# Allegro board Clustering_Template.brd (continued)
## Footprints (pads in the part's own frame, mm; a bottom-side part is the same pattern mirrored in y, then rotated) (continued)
CONM38P_MICTOR_1
  round 1.27 hole 2.388 unplated: (-11.43,0)
  oval 0.457x1.27 smd: 1(-5.715,-3.531) 2(-5.08,-3.531) 3(-4.445,-3.531) 4(-3.81,-3.531) 5(-3.175,-3.531) 6(-2.54,-3.531) 7(-1.905,-3.531) 8(-1.27,-3.531) 9(-0.635,-3.531) 10(0,-3.531) 11(0.635,-3.531) 12(1.27,-3.531) 13(1.905,-3.531) 14(2.54,-3.531) 15(3.175,-3.531) 16(3.81,-3.531) 17(4.445,-3.531) 18(5.08,-3.531) 19(5.715,-3.531) 20(5.715,3.531) 21(5.08,3.531) 22(4.445,3.531) 23(3.81,3.531) 24(3.175,3.531) 25(2.54,3.531) 26(1.905,3.531) 27(1.27,3.531) 28(0.635,3.531) 29(0,3.531) 30(-0.635,3.531) 31(-1.27,3.531) 32(-1.905,3.531) 33(-2.54,3.531) 34(-3.175,3.531) 35(-3.81,3.531) 36(-4.445,3.531) 37(-5.08,3.531) 38(-5.715,3.531)
  round 1.194 hole 0.813: 39(-5.08,0) 40(-2.54,0) 41(0,0) 42(2.54,0) 43(5.08,0)
CONM_BGA200_1
  round 1.27 hole 1.448 unplated: (-19.652,8.499) (20.137,0)
  round 1.651 hole 1.27: (-19.652,-6.35) (19.667,4)
  round 0.61 smd: A1(-17.064,-6.749) A3(-15.314,-6.749) A5(-13.564,-6.749) A7(-11.814,-6.749) A9(-10.063,-6.749) A11(-8.313,-6.749) A13(-6.563,-6.749) A15(-4.813,-6.749) A17(-3.063,-6.749) A19(-1.313,-6.749) A21(0.437,-6.749) A23(2.187,-6.749) A25(3.937,-6.749) A27(5.687,-6.749) A29(7.437,-6.749) A31(9.187,-6.749) A33(10.937,-6.749) A35(12.687,-6.749) A37(14.437,-6.749) A39(16.187,-6.749) B2(-16.187,-5.999) B4(-14.437,-5.999) B6(-12.687,-5.999) B8(-10.937,-5.999) B10(-9.187,-5.999) B12(-7.437,-5.999) B14(-5.687,-5.999) B16(-3.937,-5.999) B18(-2.187,-5.999) B20(-0.437,-5.999) B22(1.313,-5.999) B24(3.063,-5.999) B26(4.813,-5.999) B28(6.563,-5.999) B30(8.313,-5.999) B32(10.063,-5.999) B34(11.814,-5.999) B36(13.564,-5.999) B38(15.314,-5.999) B40(17.064,-5.999) C1(-17.064,-5.25) C3(-15.314,-5.25) C5(-13.564,-5.25) C7(-11.814,-5.25) C9(-10.063,-5.25) C11(-8.313,-5.25) C13(-6.563,-5.25) C15(-4.813,-5.25) C17(-3.063,-5.25) C19(-1.313,-5.25) C21(0.437,-5.25) C23(2.187,-5.25) C25(3.937,-5.25) C27(5.687,-5.25) C29(7.437,-5.25) C31(9.187,-5.25) C33(10.937,-5.25) C35(12.687,-5.25) C37(14.437,-5.25) C39(16.187,-5.25) D2(-16.187,-4.501) D4(-14.437,-4.501) D6(-12.687,-4.501) D8(-10.937,-4.501) D10(-9.187,-4.501) D12(-7.437,-4.501) D14(-5.687,-4.501) D16(-3.937,-4.501) D18(-2.187,-4.501) D20(-0.437,-4.501) D22(1.313,-4.501) D24(3.063,-4.501) D26(4.813,-4.501) D28(6.563,-4.501) D30(8.313,-4.501) D32(10.063,-4.501) D34(11.814,-4.501) D36(13.564,-4.501) D38(15.314,-4.501) D40(17.064,-4.501) E1(-17.064,-3.749) E3(-15.314,-3.749) E5(-13.564,-3.749) E7(-11.814,-3.749) E9(-10.063,-3.749) E11(-8.313,-3.749) E13(-6.563,-3.749) E15(-4.813,-3.749) E17(-3.063,-3.749) E19(-1.313,-3.749) E21(0.437,-3.749) E23(2.187,-3.749) E25(3.937,-3.749) E27(5.687,-3.749) E29(7.437,-3.749) E31(9.187,-3.749) E33(10.937,-3.749) E35(12.687,-3.749) E37(14.437,-3.749) E39(16.187,-3.749) F2(-16.187,-3) F4(-14.437,-3) F6(-12.687,-3) F8(-10.937,-3) F10(-9.187,-3) F12(-7.437,-3) F14(-5.687,-3) F16(-3.937,-3) F18(-2.187,-3) F20(-0.437,-3) F22(1.313,-3) F24(3.063,-3) F26(4.813,-3) F28(6.563,-3) F30(8.313,-3) F32(10.063,-3) F34(11.814,-3) F36(13.564,-3) F38(15.314,-3) F40(17.064,-3) G1(-17.064,-2.25) G3(-15.314,-2.25) G5(-13.564,-2.25) G7(-11.814,-2.25) G9(-10.063,-2.25) G11(-8.313,-2.25) G13(-6.563,-2.25) G15(-4.813,-2.25) G17(-3.063,-2.25) G19(-1.313,-2.25) G21(0.437,-2.25) G23(2.187,-2.25) G25(3.937,-2.25) G27(5.687,-2.25) G29(7.437,-2.25) G31(9.187,-2.25) G33(10.937,-2.25) G35(12.687,-2.25) G37(14.437,-2.25) G39(16.187,-2.25) H2(-16.187,-1.501) H4(-14.437,-1.501) H6(-12.687,-1.501) H8(-10.937,-1.501) H10(-9.187,-1.501) H12(-7.437,-1.501) H14(-5.687,-1.501) H16(-3.937,-1.501) H18(-2.187,-1.501) H20(-0.437,-1.501) H22(1.313,-1.501) H24(3.063,-1.501) H26(4.813,-1.501) H28(6.563,-1.501) H30(8.313,-1.501) H32(10.063,-1.501) H34(11.814,-1.501) H36(13.564,-1.501) H38(15.314,-1.501) H40(17.064,-1.501) J1(-17.064,-0.749) J3(-15.314,-0.749) J5(-13.564,-0.749) J7(-11.814,-0.749) J9(-10.063,-0.749) J11(-8.313,-0.749) J13(-6.563,-0.749) J15(-4.813,-0.749) J17(-3.063,-0.749) J19(-1.313,-0.749) J21(0.437,-0.749) J23(2.187,-0.749) J25(3.937,-0.749) J27(5.687,-0.749) J29(7.437,-0.749) J31(9.187,-0.749) J33(10.937,-0.749) J35(12.687,-0.749) J37(14.437,-0.749) J39(16.187,-0.749) K2(-16.187,0) K4(-14.437,0) K6(-12.687,0) K8(-10.937,0) K10(-9.187,0) K12(-7.437,0) K14(-5.687,0) K16(-3.937,0) K18(-2.187,0) K20(-0.437,0) K22(1.313,0) K24(3.063,0) K26(4.813,0) K28(6.563,0) K30(8.313,0) K32(10.063,0) K34(11.814,0) K36(13.564,0) K38(15.314,0) K40(17.064,0) L1(-17.064,0.749) L3(-15.314,0.749) L5(-13.564,0.749) L7(-11.814,0.749) L9(-10.063,0.749) L11(-8.313,0.749) L13(-6.563,0.749) L15(-4.813,0.749) L17(-3.063,0.749) L19(-1.313,0.749) L21(0.437,0.749) L23(2.187,0.749) L25(3.937,0.749) L27(5.687,0.749) L29(7.437,0.749) L31(9.187,0.749) L33(10.937,0.749) L35(12.687,0.749) L37(14.437,0.749) L39(16.187,0.749) M2(-16.187,1.501) M4(-14.437,1.501) M6(-12.687,1.501) M8(-10.937,1.501) M10(-9.187,1.501) M12(-7.437,1.501) M14(-5.687,1.501) M16(-3.937,1.501) M18(-2.187,1.501) M20(-0.437,1.501) M22(1.313,1.501) M24(3.063,1.501) M26(4.813,1.501) M28(6.563,1.501) M30(8.313,1.501) M32(10.063,1.501) M34(11.814,1.501) M36(13.564,1.501) M38(15.314,1.501) M40(17.064,1.501) N1(-17.064,2.25) N3(-15.314,2.25) N5(-13.564,2.25) N7(-11.814,2.25) N9(-10.063,2.25) N11(-8.313,2.25) N13(-6.563,2.25) N15(-4.813,2.25) N17(-3.063,2.25) N19(-1.313,2.25) N21(0.437,2.25) N23(2.187,2.25) N25(3.937,2.25) N27(5.687,2.25) N29(7.437,2.25) N31(9.187,2.25) N33(10.937,2.25) N35(12.687,2.25) N37(14.437,2.25) N39(16.187,2.25) P2(-16.187,3) P4(-14.437,3) P6(-12.687,3) P8(-10.937,3) P10(-9.187,3) P12(-7.437,3) P14(-5.687,3) P16(-3.937,3) P18(-2.187,3) P20(-0.437,3) P22(1.313,3) P24(3.063,3) P26(4.813,3) P28(6.563,3) P30(8.313,3) P32(10.063,3) P34(11.814,3) P36(13.564,3) P38(15.314,3) P40(17.064,3) R1(-17.064,3.749) R3(-15.314,3.749) R5(-13.564,3.749) R7(-11.814,3.749) R9(-10.063,3.749) R11(-8.313,3.749) R13(-6.563,3.749) R15(-4.813,3.749) R17(-3.063,3.749) R19(-1.313,3.749) R21(0.437,3.749) R23(2.187,3.749) R25(3.937,3.749) R27(5.687,3.749) R29(7.437,3.749) R31(9.187,3.749) R33(10.937,3.749) R35(12.687,3.749) R37(14.437,3.749) R39(16.187,3.749) T2(-16.187,4.501) T4(-14.437,4.501) T6(-12.687,4.501) T8(-10.937,4.501) T10(-9.187,4.501) T12(-7.437,4.501) T14(-5.687,4.501) T16(-3.937,4.501) T18(-2.187,4.501) T20(-0.437,4.501) T22(1.313,4.501) T24(3.063,4.501) T26(4.813,4.501) T28(6.563,4.501) T30(8.313,4.501) T32(10.063,4.501) T34(11.814,4.501) T36(13.564,4.501) T38(15.314,4.501) T40(17.064,4.501) U1(-17.064,5.25) U3(-15.314,5.25) U5(-13.564,5.25) U7(-11.814,5.25) U9(-10.063,5.25) U11(-8.313,5.25) U13(-6.563,5.25) U15(-4.813,5.25) U17(-3.063,5.25) U19(-1.313,5.25) U21(0.437,5.25) U23(2.187,5.25) U25(3.937,5.25) U27(5.687,5.25) U29(7.437,5.25) U31(9.187,5.25) U33(10.937,5.25) U35(12.687,5.25) U37(14.437,5.25) U39(16.187,5.25) V2(-16.187,5.999) V4(-14.437,5.999) V6(-12.687,5.999) V8(-10.937,5.999) V10(-9.187,5.999) V12(-7.437,5.999) V14(-5.687,5.999) V16(-3.937,5.999) V18(-2.187,5.999) V20(-0.437,5.999) V22(1.313,5.999) V24(3.063,5.999) V26(4.813,5.999) V28(6.563,5.999) V30(8.313,5.999) V32(10.063,5.999) V34(11.814,5.999) V36(13.564,5.999) V38(15.314,5.999) V40(17.064,5.999) W1(-17.064,6.749) W3(-15.314,6.749) W5(-13.564,6.749) W7(-11.814,6.749) W9(-10.063,6.749) W11(-8.313,6.749) W13(-6.563,6.749) W15(-4.813,6.749) W17(-3.063,6.749) W19(-1.313,6.749) W21(0.437,6.749) W23(2.187,6.749) W25(3.937,6.749) W27(5.687,6.749) W29(7.437,6.749) W31(9.187,6.749) W33(10.937,6.749) W35(12.687,6.749) W37(14.437,6.749) W39(16.187,6.749)
HDR1X2RA_SMT_100_1
  rect 1.27x3.175 smd: 1(-1.27,5.283) 2(1.27,5.283)
HDR2X6V_100SMT_1
  round 1.27 hole 1.702 unplated: (-5.08,0) (5.08,0)
  rect 1.27x3.175 smd: 1(-6.35,-2.603) 2(-6.35,2.603) 3(-3.81,-2.603) 4(-3.81,2.603) 5(-1.27,-2.603) 6(-1.27,2.603) 7(1.27,-2.603) 8(1.27,2.603) 9(3.81,-2.603) 10(3.81,2.603) 11(6.35,-2.603) 12(6.35,2.603)
RA0603_4A_1
  rect 1.016x0.508 smd: 1(-0.762,1.199) 2(-0.762,0.399) 3(-0.762,-0.399) 4(-0.762,-1.199) 5(0.762,-1.199) 6(0.762,-0.399) 7(0.762,0.399) 8(0.762,1.199)
RC0603_1
  rect 0.889x0.889 smd: 1(-0.813,0) 2(0.813,0)
RC1206_1
  rect 1.397x1.778 smd: 1(-1.664,0) 2(1.664,0)
SOIC8NB_50_1
  oval 1.905x0.635 smd: 1(-2.578,1.905) 2(-2.578,0.635) 3(-2.578,-0.635) 4(-2.578,-1.905) 5(2.578,-1.905) 6(2.578,-0.635) 7(2.578,0.635) 8(2.578,1.905)
SOT_23_1
  rect 0.762x0.889 smd: 1(-0.94,-1.003) 2(0.94,-1.003) 3(0,1.003)
TO-252AA_1
  rect 1.016x1.524 smd: 1(-2.286,-5.652) 3(2.286,-5.652)
  rect 5.715x6.223 smd: 4(0,1.638)
VREG_400G_14P_1
  round 1.27 hole 4.75 unplated: (-8.89,16.51) (41.91,16.51)
  round 1.295 hole 0.914: 1(0,0) 2(2.54,0) 3(5.08,0) 4(7.62,0) 5(10.16,0) 6(12.7,0) 7(15.24,0) 8(17.78,0) 9(20.32,0) 10(22.86,0) 11(25.4,0) 12(27.94,0) 13(30.48,0) 14(33.02,0)

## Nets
3.3V: C120.2(N2) C121.2(N2) C122.2(N2) C123.2(N2) C124.2(N2) C125.2(N2) C126.2(N2) C127.2(N2) C128.2(N2) C129.2(N2) C130.2(N2) C131.2(N2) C132.2(N2) C133.2(N2) C134.2(N2) C135.2(N2) C136.2(N2) C137.2(N2) C138.2(N2) C139.2(N2) C140.2(N2) C141.2(N2) C142.2(N2) C143.2(N2) C144.2(N2) C145.2(N2) C146.2(N2) C147.2(N2) C148.2(N2) C149.2(N2) C150.2(N2) C151.2(N2) C152.2(N2) C153.2(N2) C154.2(N2) C155.2(N2) C156.2(N2) C157.2(N2) C158.2(N2) C159.2(N2) C160.2(N2) C161.2(N2) C162.2(N2) C163.2(N2) C164.2(N2) C165.2(N2) C166.2(N2) C167.2(N2) C168.2(N2) C169.2(N2) C170.2(N2) C171.2(N2) C172.2(N2) C173.2(N2) C174.2(N2) C175.2(N2) C176.2(N2) C177.2(N2) C178.2(N2) C179.2(N2) C180.2(N2) C181.2(N2) C182.2(N2) C183.2(N2) C256.2(N2) C257.2(N2) C258.2(N2) C259.2(N2) C260.2(N2) C261.2(N2) C262.2(N2) C263.2(N2) C264.2(N2) C265.2(N2) C266.2(N2) C267.2(N2) C268.2(N2) C269.2(N2) C270.2(N2) C271.2(N2) C272.2(N2) C273.2(N2) C274.2(N2) C275.2(N2) C276.2(N2) C277.2(N2) C278.2(N2) C279.2(N2) C280.2(N2) C281.2(N2) C282.2(N2) C283.2(N2) C284.2(N2) C285.2(N2) C286.2(N2) C287.2(N2) C288.2(N2) C289.2(N2) C290.2(N2) C291.2(N2) C292.2(N2) C293.2(N2) C294.2(N2) C295.2(N2) C296.2(N2) C297.2(N2) C298.2(N2) C299.2(N2) C300.2(N2) C301.2(N2) C302.2(N2) C303.2(N2) C304.2(N2) C305.2(N2) C306.2(N2) C307.2(N2) C308.2(N2) C309.2(N2) C310.2(N2) C311.2(N2) C312.2(N2) C313.2(N2) C314.2(N2) C315.2(N2) C316.2(N2) C317.2(N2) C318.2(N2) C319.2(N2) C392.2(N2) C393.2(N2) C394.2(N2) C395.2(N2) C396.2(N2) C397.2(N2) C398.2(N2) C399.2(N2) C400.2(N2) C401.2(N2) C402.2(N2) C403.2(N2) C404.2(N2) C405.2(N2) C406.2(N2) C407.2(N2) C408.2(N2) C409.2(N2) C410.2(N2) C411.2(N2) C412.2(N2) C413.2(N2) C414.2(N2) C415.2(N2) C416.2(N2) C417.2(N2) C418.2(N2) C419.2(N2) C420.2(N2) C421.2(N2) C422.2(N2) C423.2(N2) C424.2(N2) C425.2(N2) C426.2(N2) C427.2(N2) C428.2(N2) C429.2(N2) C430.2(N2) C431.2(N2) C432.2(N2) C433.2(N2) C434.2(N2) C435.2(N2) C436.2(N2) C437.2(N2) C438.2(N2) C439.2(N2) C440.2(N2) C441.2(N2) C442.2(N2) C443.2(N2) C444.2(N2) C445.2(N2) C446.2(N2) C447.2(N2) C448.2(N2) C449.2(N2) C450.2(N2) C451.2(N2) C452.2(N2) C453.2(N2) C454.2(N2) C455.2(N2) C528.2(N2) C529.2(N2) C530.2(N2) C531.2(N2) C532.2(N2) C533.2(N2) C534.2(N2) C535.2(N2) C536.2(N2) C537.2(N2) C538.2(N2) C539.2(N2) C540.2(N2) C541.2(N2) C542.2(N2) C543.2(N2) C544.2(N2) C545.2(N2) C546.2(N2) C547.2(N2) C548.2(N2) C549.2(N2) C550.2(N2) C551.2(N2) C552.2(N2) C553.2(N2) C554.2(N2) C555.2(N2) C556.2(N2) C557.2(N2) C558.2(N2) C559.2(N2) C560.2(N2) C561.2(N2) C562.2(N2) C563.2(N2) C564.2(N2) C565.2(N2) C566.2(N2) C567.2(N2) C568.2(N2) C569.2(N2) C570.2(N2) C571.2(N2) C572.2(N2) C573.2(N2) C574.2(N2) C575.2(N2) C576.2(N2) C577.2(N2) C578.2(N2) C579.2(N2) C580.2(N2) C581.2(N2) C582.2(N2) C583.2(N2) C584.2(N2) C585.2(N2) C586.2(N2) C587.2(N2) C588.2(N2) C589.2(N2) C590.2(N2) C591.2(N2) C664.2(N2) C667.2(N2) C676.2(N2) C677.2(N2) C678.2(N2) C679.2(N2) C703.2(N2) C704.2(N2) C705.2(N2) C706.2(N2) C707.2(N2) C708.2(N2) C709.2(N2) C710.2(N2) C711.2(N2) D1.4(P) D2.4(P) J1.B2 J1.B4 J1.B6 J1.B8 J1.B10 J1.B32 J1.B34 J1.B36 J1.B38 J1.B40 J1.D2 J1.D4 J1.D6 J1.D8 J1.D10 J1.D32 J1.D34 J1.D36 J1.D38 J1.D40 J1.F2 J1.F4 J1.F6 J1.F8 J1.F10 J1.F32 J1.F34 J1.F36 J1.F38 J1.F40 J1.H2 J1.H4 J1.H6 J1.H8 J1.H10 J1.H32 J1.H34 J1.H36 J1.H38 J1.H40 J1.J3 J1.K2 J1.K4 J1.K6 J1.K8 J1.K10 J1.K32 J1.K34 J1.K36 J1.K38 J1.K40 J1.L3 J1.M2 J1.M4 J1.M6 J1.M8 J1.M10 J1.M32 J1.M34 J1.M36 J1.M38 J1.M40 J1.N3 J1.P2 J1.P4 J1.P6 J1.P8 J1.P10 J1.P32 J1.P34 J1.P36 J1.P38 J1.P40 J1.T2 J1.T4 J1.T6 J1.T8 J1.T10 J1.T32 J1.T34 J1.T36 J1.T38 J1.T40 J1.V2 J1.V4 J1.V6 J1.V8 J1.V10 J1.V32 J1.V34 J1.V36 J1.V38 J1.V40 J1.W21 P1.1 P1.3 P1.5 P1.7 P1.9(P9) P1.11 PS1.4 PS1.5 PS1.6 R1.1 R81.1 R136.1 R167.1 R170.1 R171.1 R173.1 R175.1 R176.1 R177.2(N2) R178.2(N2) R179.2(N2) R180.2(N2) R181.2(N2) R182.2(N2) R183.1 R184.1 R185.1 R186.1 RA2.4 RA3.1 RA3.2 RA3.3 RA3.4 RA4.1 RA4.2 RA4.3 RA5.1 RA5.2 RA5.3 RA6.3 RA6.4 RA7.3 RA7.4 RA8.1 RA8.2 RA8.3 RA9.2 RA10.1 RA10.2 RA11.1 RA11.2 RA11.3 RA11.4 RA12.3 RA12.4 RA13.1 RA13.2 RA13.3 RA15.1 RA15.2 RA15.3 RA15.4 RA16.1 RA16.2 RA16.3 RA18.1 RA18.4 RA23.1 RA23.4 RA27.3 RA27.4 U1.AC4 U1.AC5 U1.AC27 U1.AC28 U1.AD4 U1.AD5 U1.AD27 U1.AD28 U1.AE4 U1.AE5 U1.AE27 U1.AE28 U1.AG7 U1.AG8 U1.AG9 U1.AG14 U1.AG18 U1.AG23 U1.AG24 U1.AG25 U1.AH7 U1.AH8 U1.AH9 U1.AH14 U1.AH18 U1.AH23 U1.AH24 U1.AH25 U1.D7 U1.D8 U1.D9 U1.D14 U1.D18 U1.D23 U1.D24 U1.D25 U1.E7 U1.E8 U1.E9 U1.E14 U1.E18 U1.E23 U1.E24 U1.E25 U1.G4 U1.G5 U1.G27 U1.G28 U1.H4 U1.H5 U1.H27 U1.H28 U1.J4 U1.J5 U1.J27 U1.J28 U1.P4 U1.P5 U1.P27 U1.P28 U1.V4 U1.V5 U1.V27 U1.V28 U2.AC4 U2.AC5 U2.AC27 U2.AC28 U2.AD4 U2.AD5 U2.AD27 U2.AD28 U2.AE4 U2.AE5 U2.AE27 U2.AE28 U2.AG7 U2.AG8 U2.AG9 U2.AG14 U2.AG18 U2.AG23 U2.AG24 U2.AG25 U2.AH7 U2.AH8 U2.AH9 U2.AH14 U2.AH18 U2.AH23 U2.AH24 U2.AH25 U2.D7 U2.D8 U2.D9 U2.D14 U2.D18 U2.D23 U2.D24 U2.D25 U2.E7 U2.E8 U2.E9 U2.E14 U2.E18 U2.E23 U2.E24 U2.E25 U2.G4 U2.G5 U2.G27 U2.G28 U2.H4 U2.H5 U2.H27 U2.H28 U2.J4 U2.J5 U2.J27 U2.J28 U2.P4 U2.P5 U2.P27 U2.P28 U2.V4 U2.V5 U2.V27 U2.V28 U3.AC4 U3.AC5 U3.AC27 U3.AC28 U3.AD4 U3.AD5 U3.AD27 U3.AD28 U3.AE4 U3.AE5 U3.AE27 U3.AE28 U3.AG7 U3.AG8 U3.AG9 U3.AG14 U3.AG18 U3.AG23 U3.AG24 U3.AG25 U3.AH7 U3.AH8 U3.AH9 U3.AH14 U3.AH18 U3.AH23 U3.AH24 U3.AH25 U3.D7 U3.D8 U3.D9 U3.D14 U3.D18 U3.D23 U3.D24 U3.D25 U3.E7 U3.E8 U3.E9 U3.E14 U3.E18 U3.E23 U3.E24 U3.E25 U3.G4 U3.G5 U3.G27 U3.G28 U3.H4 U3.H5 U3.H27 U3.H28 U3.J4 U3.J5 U3.J27 U3.J28 U3.P4 U3.P5 U3.P27 U3.P28 U3.V4 U3.V5 U3.V27 U3.V28 U4.AC4 U4.AC5 U4.AC27 U4.AC28 U4.AD4 U4.AD5 U4.AD27 U4.AD28 U4.AE4 U4.AE5 U4.AE27 U4.AE28 U4.AG7 U4.AG8 U4.AG9 U4.AG14 U4.AG18 U4.AG23 U4.AG24 U4.AG25 U4.AH7 U4.AH8 U4.AH9 U4.AH14 U4.AH18 U4.AH23 U4.AH24 U4.AH25 U4.D7 U4.D8 U4.D9 U4.D14 U4.D18 U4.D23 U4.D24 U4.D25 U4.E7 U4.E8 U4.E9 U4.E14 U4.E18 U4.E23 U4.E24 U4.E25 U4.G4 U4.G5 U4.G27 U4.G28 U4.H4 U4.H5 U4.H27 U4.H28 U4.J4 U4.J5 U4.J27 U4.J28 U4.P4 U4.P5 U4.P27 U4.P28 U4.V4 U4.V5 U4.V27 U4.V28 U5.2(VCC) U6.8
GND: C1.1 C2.1 C3.1 C4.1 C5.1 C6.1 C7.1 C8.1 C9.1 C10.1 C11.1 C12.1 C13.1 C14.1 C15.1 C16.1 C17.1 C18.1 C19.1 C20.1 C21.1 C22.1 C23.1 C24.1 C25.1 C26.1 C27.1 C28.1 C29.1 C30.1 C31.1 C32.1 C33.1 C34.1 C35.1 C36.1 C37.1 C38.1 C39.1 C40.1 C41.1 C42.1 C43.1 C44.1 C45.1 C46.1 C47.1 C48.1 C49.1 C50.1 C51.1 C52.1 C53.1 C54.1 C55.1 C56.1 C57.1 C58.1 C59.1 C60.1 C61.1 C62.1 C63.1 C64.1 C65.1 C66.1 C67.1 C68.1 C69.1 C70.1 C71.1 C72.1 C73.1 C74.1 C75.1 C76.1 C77.1 C78.1 C79.1 C80.1 C81.1 C82.1 C83.1 C84.1 C85.1 C86.1 C87.1 C88.1 C89.1 C90.1 C91.1 C92.1 C93.1 C94.1 C95.1 C96.1 C97.1 C98.1 C99.1 C100.1 C101.1 C102.1 C103.1 C104.1 C105.1 C106.1 C107.1 C108.1 C109.1 C110.1 C111.1 C112.1 C113.1 C114.1 C115.1 C116.1 C117.1 C118.1 C119.1 C120.1 C121.1 C122.1 C123.1 C124.1 C125.1 C126.1 C127.1 C128.1 C129.1 C130.1 C131.1 C132.1 C133.1 C134.1 C135.1 C136.1 C137.1 C138.1 C139.1 C140.1 C141.1 C142.1 C143.1 C144.1 C145.1 C146.1 C147.1 C148.1 C149.1 C150.1 C151.1 C152.1 C153.1 C154.1 C155.1 C156.1 C157.1 C158.1 C159.1 C160.1 C161.1 C162.1 C163.1 C164.1 C165.1 C166.1 C167.1 C168.1 C169.1 C170.1 C171.1 C172.1 C173.1 C174.1 C175.1 C176.1 C177.1 C178.1 C179.1 C180.1 C181.1 C182.1 C183.1 C184.1 C185.1 C186.1 C187.1 C188.1 C189.1 C190.1 C191.1 C192.1 C193.1 C194.1 C195.1 C196.1 C197.1 C198.1 C199.1 C200.1 C201.1 C202.1 C203.1 C204.1 C205.1 C206.1 C207.1 C208.1 C209.1 C210.1 C211.1 C212.1 C213.1 C214.1 C215.1 C216.1 C217.1 C218.1 C219.1 C220.1 C221.1 C222.1 C223.1 C224.1 C225.1 C226.1 C227.1 C228.1 C229.1 C230.1 C231.1 C232.1 C233.1 C234.1 C235.1 C236.1 C237.1 C238.1 C239.1 C240.1 C241.1 C242.1 C243.1 C244.1 C245.1 C246.1 C247.1 C248.1 C249.1 C250.1 C251.1 C252.1 C253.1 C254.1 C255.1 C256.1 C257.1 C258.1 C259.1 C260.1 C261.1 C262.1 C263.1 C264.1 C265.1 C266.1 C267.1 C268.1 C269.1 C270.1 C271.1 C272.1 C273.1 C274.1 C275.1 C276.1 C277.1 C278.1 C279.1 C280.1 C281.1 C282.1 C283.1 C284.1 C285.1 C286.1 C287.1 C288.1 C289.1 C290.1 C291.1 C292.1 C293.1 C294.1 C295.1 C296.1 C297.1 C298.1 C299.1 C300.1 C301.1 C302.1 C303.1 C304.1 C305.1 C306.1 C307.1 C308.1 C309.1 C310.1 C311.1 C312.1 C313.1 C314.1 C315.1 C316.1 C317.1 C318.1 C319.1 C320.1 C321.1 C322.1 C323.1 C324.1 C325.1 C326.1 C327.1 C328.1 C329.1 C330.1 C331.1 C332.1 C333.1 C334.1 C335.1 C336.1 C337.1 C338.1 C339.1 C340.1 C341.1 C342.1 C343.1 C344.1 C345.1 C346.1 C347.1 C348.1 C349.1 C350.1 C351.1 C352.1 C353.1 C354.1 C355.1 C356.1 C357.1 C358.1 C359.1 C360.1 C361.1 C362.1 C363.1 C364.1 C365.1 C366.1 C367.1 C368.1 C369.1 C370.1 C371.1 C372.1 C373.1 C374.1 C375.1 C376.1 C377.1 C378.1 C379.1 C380.1 C381.1 C382.1 C383.1 C384.1 C385.1 C386.1 C387.1 C388.1 C389.1 C390.1 C391.1 C392.1 C393.1 C394.1 C395.1 C396.1 C397.1 C398.1 C399.1 C400.1 C401.1 C402.1 C403.1 C404.1 C405.1 C406.1 C407.1 C408.1 C409.1 C410.1 C411.1 C412.1 C413.1 C414.1 C415.1 C416.1 C417.1 C418.1 C419.1 C420.1 C421.1 C422.1 C423.1 C424.1 C425.1 C426.1 C427.1 C428.1 C429.1 C430.1 C431.1 C432.1 C433.1 C434.1 C435.1 C436.1 C437.1 C438.1 C439.1 C440.1 C441.1 C442.1 C443.1 C444.1 C445.1 C446.1 C447.1 C448.1 C449.1 C450.1 C451.1 C452.1 C453.1 C454.1 C455.1 C456.1 C457.1 C458.1 C459.1 C460.1 C461.1 C462.1 C463.1 C464.1 C465.1 C466.1 C467.1 C468.1 C469.1 C470.1 C471.1 C472.1 C473.1 C474.1 C475.1 C476.1 C477.1 C478.1 C479.1 C480.1 C481.1 C482.1 C483.1 C484.1 C485.1 C486.1 C487.1 C488.1 C489.1 C490.1 C491.1 C492.1 C493.1 C494.1 C495.1 C496.1 C497.1 C498.1 C499.1 C500.1 C501.1 C502.1 C503.1 C504.1 C505.1 C506.1 C507.1 C508.1 C509.1 C510.1 C511.1 C512.1 C513.1 C514.1 C515.1 C516.1 C517.1 C518.1 C519.1 C520.1 C521.1 C522.1 C523.1 C524.1 C525.1 C526.1 C527.1 C528.1 C529.1 C530.1 C531.1 C532.1 C533.1 C534.1 C535.1 C536.1 C537.1 C538.1 C539.1 C540.1 C541.1 C542.1 C543.1 C544.1 C545.1 C546.1 C547.1 C548.1 C549.1 C550.1 C551.1 C552.1 C553.1 C554.1 C555.1 C556.1 C557.1 C558.1 C559.1 C560.1 C561.1 C562.1 C563.1 C564.1 C565.1 C566.1 C567.1 C568.1 C569.1 C570.1 C571.1 C572.1 C573.1 C574.1 C575.1 C576.1 C577.1 C578.1 C579.1 C580.1 C581.1 C582.1 C583.1 C584.1 C585.1 C586.1 C587.1 C588.1 C589.1 C590.1 C591.1 C592.1 C593.1 C594.1 C595.1 C596.1 C597.1 C598.1 C599.1 C600.1 C601.1 C602.1 C603.1 C604.1 C605.1 C606.1 C607.1 C608.1 C609.1 C610.1 C611.1 C612.1 C613.1 C614.1 C615.1 C616.1 C617.1 C618.1 C619.1 C620.1 C621.1 C622.1 C623.1 C624.1 C625.1 C626.1 C627.1 C628.1 C629.1 C630.1 C631.1 C632.1 C633.1 C634.1 C635.1 C636.1 C637.1 C638.1 C639.1 C640.1 C641.1 C642.1 C643.1 C644.1 C645.1 C646.1 C647.1 C648.1 C649.1 C650.1 C651.1 C652.1 C653.1 C654.1 C655.1 C656.1 C657.1 C658.1 C659.1 C660.1 C661.1 C662.1 C663.1 C664.1 C665.1 C666.1 C667.1 C668.1 C669.1 C670.1 C671.1 C672.1 C673.1 C674.1 C675.1 C676.1 C677.1 C678.1 C679.1 C680.1 C681.1 C682.1 C683.1 C684.1 C685.1 C686.1 C687.1 C688.1 C689.1 C690.1 C691.1 C692.1 C693.1 C694.1 C703.1 C704.1 C705.1 C706.1 C707.1 C708.1 C709.1 C710.1 C711.1 J1.B12 J1.B14 J1.B16 J1.B18 J1.B20 J1.B22 J1.B24 J1.B26 J1.B28 J1.B30 J1.D12 J1.D14 J1.D16 J1.D18 J1.D20 J1.D22 J1.D24 J1.D26 J1.D28 J1.D30 J1.F12 J1.F14 J1.F16 J1.F18 J1.F20 J1.F22 J1.F24 J1.F26 J1.F28 J1.F30 J1.H12 J1.H14 J1.H16 J1.H18 J1.H20 J1.H22 J1.H24 J1.H26 J1.H28 J1.H30 J1.K12 J1.K14 J1.K16 J1.K18 J1.K20 J1.K22 J1.K24 J1.K26 J1.K28 J1.K30 J1.M12 J1.M14 J1.M16 J1.M18 J1.M20 J1.M22 J1.M24 J1.M26 J1.M28 J1.M30 J1.N13 J1.N15 J1.N17 J1.N19 J1.P12 J1.P14 J1.P16 J1.P18 J1.P20 J1.P22 J1.P24 J1.P26 J1.P28 J1.P30 J1.T12 J1.T14 J1.T16 J1.T18 J1.T20 J1.T22 J1.T24 J1.T26 J1.T28 J1.T30 J1.U13 J1.U15 J1.U17 J1.U19 J1.U21 J1.U23 J1.U25 J1.U27 J1.U29 J1.V12 J1.V14 J1.V16 J1.V18 J1.V20 J1.V22 J1.V24 J1.V26 J1.V28 J1.V30 J1.W3 J2.39 J2.40 J2.41 J2.42 J2.43 J3.39 J3.40 J3.41 J3.42 J3.43 J4.39 J4.40 J4.41 J4.42 J4.43 J5.39 J5.40 J5.41 J5.42 J5.43 J6.39 J6.40 J6.41 J6.42 J6.43 J7.2(P2) P1.2 P1.4 P1.6 P1.8 P1.10 P1.12 PS1.7 PS1.8 PS1.9 PS1.10 Q1.2(S) R87.1 R128.2(N2) R129.2(N2) R130.2(N2) R131.2(N2) R132.2(N2) R140.2(N2) R141.2(N2) R146.1 R147.1 R166.1 R168.1 R169.1 R172.1 R174.1 RA1.1 RA1.2 RA2.1 RA2.2 RA2.3 RA4.4 RA5.4 RA6.1 RA6.2 RA7.1 RA7.2 RA8.4 RA9.1 RA9.3 RA9.4 RA10.3 RA10.4 RA12.1 RA12.2 RA13.4 RA14.1 RA14.2 RA14.3 RA14.4 RA16.4 RA18.2 RA18.3 RA19.1 RA19.2 RA19.3 RA19.4 RA20.1 RA20.2 RA20.3 RA20.4 RA21.1 RA21.2 RA21.3 RA21.4 RA22.1 RA22.2 RA23.2 RA23.3 RA24.1 RA24.2 RA24.3 RA24.4 RA25.1 RA25.2 RA25.3 RA25.4 RA26.1 RA26.2 RA27.1 RA27.2 RA28.1 RA28.2 RA28.3 RA28.4 RA29.1 RA29.2 RA29.3 RA29.4 RA30.1 RA30.2 RA31.1 RA31.2 RA31.3 RA31.4 RA32.1 RA32.2 RA32.3 RA32.4 RA33.1 RA33.2 RA34.1 RA34.2 RA34.3 RA34.4 U1.A1 U1.A2 U1.A3 U1.A4 U1.A25 U1.A26 U1.A27 U1.A28 U1.A29 U1.A30 U1.A31 U1.AF4 U1.AF5 U1.AF27 U1.AF28 U1.AG4 U1.AG5 U1.AG6 U1.AG13 U1.AG19 U1.AG26 U1.AG27 U1.AG28 U1.AH1 U1.AH4 U1.AH5 U1.AH6 U1.AH13 U1.AH19 U1.AH26 U1.AH27 U1.AH28 U1.AH31 U1.AJ1 U1.AJ2 U1.AJ3 U1.AJ29 U1.AJ30 U1.AJ31 U1.AK1 U1.AK2 U1.AK3 U1.AK29 U1.AK30 U1.AK31 U1.AL1 U1.AL2 U1.AL3 U1.AL4 U1.AL27 U1.AL28 U1.AL29 U1.AL30 U1.AL31 U1.B1 U1.B2 U1.B3 U1.B4 U1.B28 U1.B29 U1.B30 U1.B31 U1.C1 U1.C2 U1.C3 U1.C29 U1.C30 U1.C31 U1.D1 U1.D4 U1.D5 U1.D6 U1.D13 U1.D19 U1.D26 U1.D27 U1.D28 U1.D30 U1.D31 U1.E1 U1.E4 U1.E5 U1.E6 U1.E13 U1.E19 U1.E26 U1.E27 U1.E28 U1.E31 U1.F4 U1.F5 U1.F27 U1.F28 U1.N4 U1.N5 U1.N13 U1.N14 U1.N15 U1.N16 U1.N17 U1.N18 U1.N19 U1.N27 U1.N28 U1.P13 U1.P14 U1.P15 U1.P16 U1.P17 U1.P18 U1.P19 U1.R13 U1.R14 U1.R15 U1.R16 U1.R17 U1.R18 U1.R19 U1.T13 U1.T14 U1.T15 U1.T16 U1.T17 U1.T18 U1.T19 U1.U13 U1.U14 U1.U15 U1.U16 U1.U17 U1.U18 U1.U19 U1.V13 U1.V14 U1.V15 U1.V16 U1.V17 U1.V18 U1.V19 U1.W4 U1.W5 U1.W13 U1.W14 U1.W15 U1.W16 U1.W17 U1.W18 U1.W19 U1.W27 U1.W28 U2.A1 U2.A2 U2.A3 U2.A4 U2.A25 U2.A26 U2.A27 U2.A28 U2.A29 U2.A30 U2.A31 U2.AF4 U2.AF5 U2.AF27 U2.AF28 U2.AG4 U2.AG5 U2.AG6 U2.AG13 U2.AG19 U2.AG26 U2.AG27 U2.AG28 U2.AH1 U2.AH4 U2.AH5 U2.AH6 U2.AH13 U2.AH19 U2.AH26 U2.AH27 U2.AH28 U2.AH31 U2.AJ1 U2.AJ2 U2.AJ3 U2.AJ29 U2.AJ30 U2.AJ31 U2.AK1 U2.AK2 U2.AK3 U2.AK29 U2.AK30 U2.AK31 U2.AL1 U2.AL2 U2.AL3 U2.AL4 U2.AL27 U2.AL28 U2.AL29 U2.AL30 U2.AL31 U2.B1 U2.B2 U2.B3 U2.B4 U2.B28 U2.B29 U2.B30 U2.B31 U2.C1 U2.C2 U2.C3 U2.C29 U2.C30 U2.C31 U2.D1 U2.D4 U2.D5 U2.D6 U2.D13 U2.D19 U2.D26 U2.D27 U2.D28 U2.D30 U2.D31 U2.E1 U2.E4 U2.E5 U2.E6 U2.E13 U2.E19 U2.E26 U2.E27 U2.E28 U2.E31 U2.F4 U2.F5 U2.F27 U2.F28 U2.N4 U2.N5 U2.N13 U2.N14 U2.N15 U2.N16 U2.N17 U2.N18 U2.N19 U2.N27 U2.N28 U2.P13 U2.P14 U2.P15 U2.P16 U2.P17 U2.P18 U2.P19 U2.R13 U2.R14 U2.R15 U2.R16 U2.R17 U2.R18 U2.R19 U2.T13 U2.T14 U2.T15 U2.T16 U2.T17 U2.T18 U2.T19 U2.U13 U2.U14 U2.U15 U2.U16 U2.U17 U2.U18 U2.U19 U2.V13 U2.V14 U2.V15 U2.V16 U2.V17 U2.V18 U2.V19 U2.W4 U2.W5 U2.W13 U2.W14 U2.W15 U2.W16 U2.W17 U2.W18 U2.W19 U2.W27 U2.W28 U3.A1 U3.A2 U3.A3 U3.A4 U3.A25 U3.A26 U3.A27 U3.A28 U3.A29 U3.A30 U3.A31 U3.AF4 U3.AF5 U3.AF27 U3.AF28 U3.AG4 U3.AG5 U3.AG6 U3.AG13 U3.AG19 U3.AG26 U3.AG27 U3.AG28 U3.AH1 U3.AH4 U3.AH5 U3.AH6 U3.AH13 U3.AH19 U3.AH26 U3.AH27 U3.AH28 U3.AH31 U3.AJ1 U3.AJ2 U3.AJ3 U3.AJ29 U3.AJ30 U3.AJ31 U3.AK1 U3.AK2 U3.AK3 U3.AK29 U3.AK30 U3.AK31 U3.AL1 U3.AL2 U3.AL3 U3.AL4 U3.AL27 U3.AL28 U3.AL29 U3.AL30 U3.AL31 U3.B1 U3.B2 U3.B3 U3.B4 U3.B28 U3.B29 U3.B30 U3.B31 U3.C1 U3.C2 U3.C3 U3.C29 U3.C30 U3.C31 U3.D1 U3.D4 U3.D5 U3.D6 U3.D13 U3.D19 U3.D26 U3.D27 U3.D28 U3.D30 U3.D31 U3.E1 U3.E4 U3.E5 U3.E6 U3.E13 U3.E19 U3.E26 U3.E27 U3.E28 U3.E31 U3.F4 U3.F5 U3.F27 U3.F28 U3.N4 U3.N5 U3.N13 U3.N14 U3.N15 U3.N16 U3.N17 U3.N18 U3.N19 U3.N27 U3.N28 U3.P13 U3.P14 U3.P15 U3.P16 U3.P17 U3.P18 U3.P19 U3.R13 U3.R14 U3.R15 U3.R16 U3.R17 U3.R18 U3.R19 U3.T13 U3.T14 U3.T15 U3.T16 U3.T17 U3.T18 U3.T19 U3.U13 U3.U14 U3.U15 U3.U16 U3.U17 U3.U18 U3.U19 U3.V13 U3.V14 U3.V15 U3.V16 U3.V17 U3.V18 U3.V19 U3.W4 U3.W5 U3.W13 U3.W14 U3.W15 U3.W16 U3.W17 U3.W18 U3.W19 U3.W27 U3.W28 U4.A1 U4.A2 U4.A3 U4.A4 U4.A25 U4.A26 U4.A27 U4.A28 U4.A29 U4.A30 U4.A31 U4.AF4 U4.AF5 U4.AF27 U4.AF28 U4.AG4 U4.AG5 U4.AG6 U4.AG13 U4.AG19 U4.AG26 U4.AG27 U4.AG28 U4.AH1 U4.AH4 U4.AH5 U4.AH6 U4.AH13 U4.AH19 U4.AH26 U4.AH27 U4.AH28 U4.AH31 U4.AJ1 U4.AJ2 U4.AJ3 U4.AJ29 U4.AJ30 U4.AJ31 U4.AK1 U4.AK2 U4.AK3 U4.AK29 U4.AK30 U4.AK31 U4.AL1 U4.AL2 U4.AL3 U4.AL4 U4.AL27 U4.AL28 U4.AL29 U4.AL30 U4.AL31 U4.B1 U4.B2 U4.B3 U4.B4 U4.B28 U4.B29 U4.B30 U4.B31 U4.C1 U4.C2 U4.C3 U4.C29 U4.C30 U4.C31 U4.D1 U4.D4 U4.D5 U4.D6 U4.D13 U4.D19 U4.D26 U4.D27 U4.D28 U4.D30 U4.D31 U4.E1 U4.E4 U4.E5 U4.E6 U4.E13 U4.E19 U4.E26 U4.E27 U4.E28 U4.E31 U4.F4 U4.F5 U4.F27 U4.F28 U4.N4 U4.N5 U4.N13 U4.N14 U4.N15 U4.N16 U4.N17 U4.N18 U4.N19 U4.N27 U4.N28 U4.P13 U4.P14 U4.P15 U4.P16 U4.P17 U4.P18 U4.P19 U4.R13 U4.R14 U4.R15 U4.R16 U4.R17 U4.R18 U4.R19 U4.T13 U4.T14 U4.T15 U4.T16 U4.T17 U4.T18 U4.T19 U4.U13 U4.U14 U4.U15 U4.U16 U4.U17 U4.U18 U4.U19 U4.V13 U4.V14 U4.V15 U4.V16 U4.V17 U4.V18 U4.V19 U4.W4 U4.W5 U4.W13 U4.W14 U4.W15 U4.W16 U4.W17 U4.W18 U4.W19 U4.W27 U4.W28 U5.3 U6.4
VDD_CORE: C184.2(N2) C185.2(N2) C186.2(N2) C187.2(N2) C188.2(N2) C189.2(N2) C190.2(N2) C191.2(N2) C192.2(N2) C193.2(N2) C194.2(N2) C195.2(N2) C196.2(N2) C197.2(N2) C198.2(N2) C199.2(N2) C200.2(N2) C201.2(N2) C202.2(N2) C203.2(N2) C204.2(N2) C205.2(N2) C206.2(N2) C207.2(N2) C208.2(N2) C209.2(N2) C210.2(N2) C211.2(N2) C212.2(N2) C213.2(N2) C214.2(N2) C215.2(N2) C216.2(N2) C217.2(N2) C218.2(N2) C219.2(N2) C220.2(N2) C221.2(N2) C222.2(N2) C223.2(N2) C224.2(N2) C225.2(N2) C226.2(N2) C227.2(N2) C228.2(N2) C229.2(N2) C230.2(N2) C231.2(N2) C232.2(N2) C233.2(N2) C234.2(N2) C235.2(N2) C236.2(N2) C237.2(N2) C238.2(N2) C239.2(N2) C240.2(N2) C241.2(N2) C242.2(N2) C243.2(N2) C244.2(N2) C245.2(N2) C246.2(N2) C247.2(N2) C248.2(N2) C249.2(N2) C250.2(N2) C251.2(N2) C252.2(N2) C253.2(N2) C254.2(N2) C255.2(N2) C320.2(N2) C321.2(N2) C322.2(N2) C323.2(N2) C324.2(N2) C325.2(N2) C326.2(N2) C327.2(N2) C328.2(N2) C329.2(N2) C330.2(N2) C331.2(N2) C332.2(N2) C333.2(N2) C334.2(N2) C335.2(N2) C336.2(N2) C337.2(N2) C338.2(N2) C339.2(N2) C340.2(N2) C341.2(N2) C342.2(N2) C343.2(N2) C344.2(N2) C345.2(N2) C346.2(N2) C347.2(N2) C348.2(N2) C349.2(N2) C350.2(N2) C351.2(N2) C352.2(N2) C353.2(N2) C354.2(N2) C355.2(N2) C356.2(N2) C357.2(N2) C358.2(N2) C359.2(N2) C360.2(N2) C361.2(N2) C362.2(N2) C363.2(N2) C364.2(N2) C365.2(N2) C366.2(N2) C367.2(N2) C368.2(N2) C369.2(N2) C370.2(N2) C371.2(N2) C372.2(N2) C373.2(N2) C374.2(N2) C375.2(N2) C376.2(N2) C377.2(N2) C378.2(N2) C379.2(N2) C380.2(N2) C381.2(N2) C382.2(N2) C383.2(N2) C384.2(N2) C385.2(N2) C386.2(N2) C387.2(N2) C388.2(N2) C389.2(N2) C390.2(N2) C391.2(N2) C456.2(N2) C457.2(N2) C458.2(N2) C459.2(N2) C460.2(N2) C461.2(N2) C462.2(N2) C463.2(N2) C464.2(N2) C465.2(N2) C466.2(N2) C467.2(N2) C468.2(N2) C469.2(N2) C470.2(N2) C471.2(N2) C472.2(N2) C473.2(N2) C474.2(N2) C475.2(N2) C476.2(N2) C477.2(N2) C478.2(N2) C479.2(N2) C480.2(N2) C481.2(N2) C482.2(N2) C483.2(N2) C484.2(N2) C485.2(N2) C486.2(N2) C487.2(N2) C488.2(N2) C489.2(N2) C490.2(N2) C491.2(N2) C492.2(N2) C493.2(N2) C494.2(N2) C495.2(N2) C496.2(N2) C497.2(N2) C498.2(N2) C499.2(N2) C500.2(N2) C501.2(N2) C502.2(N2) C503.2(N2) C504.2(N2) C505.2(N2) C506.2(N2) C507.2(N2) C508.2(N2) C509.2(N2) C510.2(N2) C511.2(N2) C512.2(N2) C513.2(N2) C514.2(N2) C515.2(N2) C516.2(N2) C517.2(N2) C518.2(N2) C519.2(N2) C520.2(N2) C521.2(N2) C522.2(N2) C523.2(N2) C524.2(N2) C525.2(N2) C526.2(N2) C527.2(N2) C592.2(N2) C593.2(N2) C594.2(N2) C595.2(N2) C596.2(N2) C597.2(N2) C598.2(N2) C599.2(N2) C600.2(N2) C601.2(N2) C602.2(N2) C603.2(N2) C604.2(N2) C605.2(N2) C606.2(N2) C607.2(N2) C608.2(N2) C609.2(N2) C610.2(N2) C611.2(N2) C612.2(N2) C613.2(N2) C614.2(N2) C615.2(N2) C616.2(N2) C617.2(N2) C618.2(N2) C619.2(N2) C620.2(N2) C621.2(N2) C622.2(N2) C623.2(N2) C624.2(N2) C625.2(N2) C626.2(N2) C627.2(N2) C628.2(N2) C629.2(N2) C630.2(N2) C631.2(N2) C632.2(N2) C633.2(N2) C634.2(N2) C635.2(N2) C636.2(N2) C637.2(N2) C638.2(N2) C639.2(N2) C640.2(N2) C641.2(N2) C642.2(N2) C643.2(N2) C644.2(N2) C645.2(N2) C646.2(N2) C647.2(N2) C648.2(N2) C649.2(N2) C650.2(N2) C651.2(N2) C652.2(N2) C653.2(N2) C654.2(N2) C655.2(N2) C656.2(N2) C657.2(N2) C658.2(N2) C659.2(N2) C660.2(N2) C661.2(N2) C662.2(N2) C663.2(N2) C665.2(N2) C666.2(N2) C680.2(N2) C681.2(N2) C682.2(N2) C683.2(N2) D1.1 D1.3 D2.1 D2.3 PS1.11 PS1.12 PS1.13 R135.2(N2) R156.2(N2) R157.2(N2) R158.2(N2) R159.2(N2) U1.AA4 U1.AA5 U1.AA27 U1.AA28 U1.AB4 U1.AB5 U1.AB27 U1.AB28 U1.AG10 U1.AG11 U1.AG12 U1.AG15 U1.AG16 U1.AG17 U1.AG20 U1.AG21 U1.AG22 U1.AH10 U1.AH11 U1.AH12 U1.AH15 U1.AH16 U1.AH17 U1.AH20 U1.AH21 U1.AH22 U1.D10 U1.D11 U1.D12 U1.D15 U1.D16 U1.D17 U1.D20 U1.D21 U1.D22 U1.E10 U1.E11 U1.E12 U1.E15 U1.E16 U1.E17 U1.E20 U1.E21 U1.E22 U1.K4 U1.K5 U1.K27 U1.K28 U1.L4 U1.L5 U1.L27 U1.L28 U1.M4 U1.M5 U1.M27 U1.M28 U1.R4 U1.R5 U1.R27 U1.T4 U1.T5 U1.T27 U1.T28 U1.U4 U1.U5 U1.U27 U1.U28 U1.Y4 U1.Y5 U1.Y27 U1.Y28 U2.AA4 U2.AA5 U2.AA27 U2.AA28 U2.AB4 U2.AB5 U2.AB27 U2.AB28 U2.AG10 U2.AG11 U2.AG12 U2.AG15 U2.AG16 U2.AG17 U2.AG20 U2.AG21 U2.AG22 U2.AH10 U2.AH11 U2.AH12 U2.AH15 U2.AH16 U2.AH17 U2.AH20 U2.AH21 U2.AH22 U2.D10 U2.D11 U2.D12 U2.D15 U2.D16 U2.D17 U2.D20 U2.D21 U2.D22 U2.E10 U2.E11 U2.E12 U2.E15 U2.E16 U2.E17 U2.E20 U2.E21 U2.E22 U2.K4 U2.K5 U2.K27 U2.K28 U2.L4 U2.L5 U2.L27 U2.L28 U2.M4 U2.M5 U2.M27 U2.M28 U2.R4 U2.R5 U2.R27 U2.T4 U2.T5 U2.T27 U2.T28 U2.U4 U2.U5 U2.U27 U2.U28 U2.Y4 U2.Y5 U2.Y27 U2.Y28 U3.AA4 U3.AA5 U3.AA27 U3.AA28 U3.AB4 U3.AB5 U3.AB27 U3.AB28 U3.AG10 U3.AG11 U3.AG12 U3.AG15 U3.AG16 U3.AG17 U3.AG20 U3.AG21 U3.AG22 U3.AH10 U3.AH11 U3.AH12 U3.AH15 U3.AH16 U3.AH17 U3.AH20 U3.AH21 U3.AH22 U3.D10 U3.D11 U3.D12 U3.D15 U3.D16 U3.D17 U3.D20 U3.D21 U3.D22 U3.E10 U3.E11 U3.E12 U3.E15 U3.E16 U3.E17 U3.E20 U3.E21 U3.E22 U3.K4 U3.K5 U3.K27 U3.K28 U3.L4 U3.L5 U3.L27 U3.L28 U3.M4 U3.M5 U3.M27 U3.M28 U3.R4 U3.R5 U3.R27 U3.T4 U3.T5 U3.T27 U3.T28 U3.U4 U3.U5 U3.U27 U3.U28 U3.Y4 U3.Y5 U3.Y27 U3.Y28 U4.AA4 U4.AA5 U4.AA27 U4.AA28 U4.AB4 U4.AB5 U4.AB27 U4.AB28 U4.AG10 U4.AG11 U4.AG12 U4.AG15 U4.AG16 U4.AG17 U4.AG20 U4.AG21 U4.AG22 U4.AH10 U4.AH11 U4.AH12 U4.AH15 U4.AH16 U4.AH17 U4.AH20 U4.AH21 U4.AH22 U4.D10 U4.D11 U4.D12 U4.D15 U4.D16 U4.D17 U4.D20 U4.D21 U4.D22 U4.E10 U4.E11 U4.E12 U4.E15 U4.E16 U4.E17 U4.E20 U4.E21 U4.E22 U4.K4 U4.K5 U4.K27 U4.K28 U4.L4 U4.L5 U4.L27 U4.L28 U4.M4 U4.M5 U4.M27 U4.M28 U4.R4 U4.R5 U4.R27 U4.T4 U4.T5 U4.T27 U4.T28 U4.U4 U4.U5 U4.U27 U4.U28 U4.Y4 U4.Y5 U4.Y27 U4.Y28
$2I1094\ACT_CDQ0: C37.2(N2) R117.1
$2I1094\ACT_CDQ1: C32.2(N2) R116.1
$2I1094\ACT_CDQ2: C28.2(N2) R115.1
$2I1094\ACT_CDQ3: C24.2(N2) R114.1
$2I1094\ACT_CDQ4: C36.2(N2) R110.1
$2I1094\ACT_CDQ5: C31.2(N2) R113.1
$2I1094\ACT_CDQ6: C27.2(N2) R112.1
$2I1094\ACT_CDQ7: C23.2(N2) R111.1
$2I1094\ACT_CDQ8: C35.2(N2) R125.1
$2I1094\ACT_CDQ9: C30.2(N2) R124.1
$2I1094\ACT_CDQ10: C26.2(N2) R123.1
$2I1094\ACT_CDQ11: C22.2(N2) R122.1
$2I1094\ACT_CDQ12: C34.2(N2) R118.1
$2I1094\ACT_CDQ13: C29.2(N2) R121.1
$2I1094\ACT_CDQ14: C25.2(N2) R120.1
$2I1094\ACT_CDQ15: C21.2(N2) R119.1
$2I1094\ACT_CDQ16: C20.2(N2) R91.1
$2I1094\ACT_CDQ17: C15.2(N2) R90.1
$2I1094\ACT_CDQ18: C10.2(N2) R89.1
$2I1094\ACT_CDQ19: C5.2(N2) R88.1
$2I1094\ACT_CDQ20: C19.2(N2) R99.1
$2I1094\ACT_CDQ21: C14.2(N2) R98.1
$2I1094\ACT_CDQ22: C9.2(N2) R97.1
$2I1094\ACT_CDQ23: C4.2(N2) R96.1
$2I1094\ACT_CDQ24: C18.2(N2) R92.1
$2I1094\ACT_CDQ25: C13.2(N2) R95.1
$2I1094\ACT_CDQ26: C8.2(N2) R94.1
$2I1094\ACT_CDQ27: C3.2(N2) R93.1
$2I1094\ACT_CDQ28: C17.2(N2) R106.1
$2I1094\ACT_CDQ29: C12.2(N2) R107.1
$2I1094\ACT_CDQ30: C7.2(N2) R105.1
$2I1094\ACT_CDQ31: C2.2(N2) R104.1
$2I1094\ACT_CDQ32: C16.2(N2) R100.1
$2I1094\ACT_CDQ33: C11.2(N2) R103.1
$2I1094\ACT_CDQ34: C6.2(N2) R102.1
$2I1094\ACT_CDQ35: C1.2(N2) R101.1
$2I1094\ACT_CRDY: C38.2(N2) R109.1
$2I1094\ACT_CTA: C33.2(N2) R108.1
$2I1098\$2N920: C63.2(N2) R26.1
$2I1098\$2N921: C64.2(N2) R27.1
$2I1098\$2N922: C65.2(N2) R28.1
$2I1098\$2N923: C66.2(N2) R29.1
$2I1098\$2N924: C67.2(N2) R30.1
$2I1098\$2N925: C68.2(N2) R31.1
$2I1098\$2N926: C69.2(N2) R32.1
$2I1098\$2N927: C70.2(N2) R33.1
$2I1098\$2N928: C71.2(N2) R34.1
$2I1098\$2N929: C72.2(N2) R35.1
$2I1098\$2N930: C73.2(N2) R36.1
$2I1098\$2N931: C74.2(N2) R37.1
$2I1098\$2N932: C51.2(N2) R14.1
$2I1098\$2N933: C52.2(N2) R15.1
$2I1098\$2N934: C53.2(N2) R16.1
$2I1098\$2N935: C54.2(N2) R17.1
$2I1098\$2N936: C55.2(N2) R18.1
$2I1098\$2N937: C56.2(N2) R19.1
$2I1098\$2N938: C57.2(N2) R20.1
$2I1098\$2N939: C58.2(N2) R21.1
$2I1098\$2N940: C59.2(N2) R22.1
$2I1098\$2N941: C60.2(N2) R23.1
$2I1098\$2N942: C61.2(N2) R24.1
$2I1098\$2N943: C62.2(N2) R25.1
$2I1098\$2N944: C39.2(N2) R2.1
$2I1098\$2N945: C40.2(N2) R3.1
$2I1098\$2N946: C41.2(N2) R4.1
$2I1098\$2N947: C42.2(N2) R5.1
$2I1098\$2N948: C43.2(N2) R6.1
$2I1098\$2N949: C44.2(N2) R7.1
$2I1098\$2N950: C45.2(N2) R8.1
$2I1098\$2N951: C46.2(N2) R9.1
$2I1098\$2N952: C47.2(N2) R10.1
$2I1098\$2N953: C48.2(N2) R11.1
$2I1098\$2N954: C49.2(N2) R12.1
$2I1098\$2N955: C50.2(N2) R13.1
$2I1098\$3N922: C99.2(N2) R62.1
$2I1098\$3N923: C100.2(N2) R63.1
$2I1098\$3N924: C101.2(N2) R64.1
$2I1098\$3N925: C102.2(N2) R65.1
$2I1098\$3N926: C103.2(N2) R66.1
$2I1098\$3N927: C104.2(N2) R67.1
$2I1098\$3N928: C105.2(N2) R68.1
$2I1098\$3N929: C106.2(N2) R69.1
$2I1098\$3N930: C107.2(N2) R70.1
$2I1098\$3N931: C108.2(N2) R71.1
$2I1098\$3N932: C109.2(N2) R72.1
$2I1098\$3N933: C110.2(N2) R73.1
$2I1098\$3N934: C87.2(N2) R50.1
$2I1098\$3N935: C88.2(N2) R51.1
$2I1098\$3N936: C89.2(N2) R52.1
$2I1098\$3N937: C90.2(N2) R53.1
$2I1098\$3N938: C91.2(N2) R54.1
$2I1098\$3N939: C92.2(N2) R55.1
$2I1098\$3N940: C93.2(N2) R56.1
$2I1098\$3N941: C94.2(N2) R57.1
$2I1098\$3N942: C95.2(N2) R58.1
$2I1098\$3N943: C96.2(N2) R59.1
$2I1098\$3N944: C97.2(N2) R60.1
$2I1098\$3N945: C98.2(N2) R61.1
$2I1098\$3N946: C75.2(N2) R38.1
$2I1098\$3N947: C76.2(N2) R39.1
$2I1098\$3N948: C77.2(N2) R40.1
$2I1098\$3N949: C78.2(N2) R41.1
$2I1098\$3N950: C79.2(N2) R42.1
$2I1098\$3N951: C80.2(N2) R43.1
$2I1098\$3N952: C81.2(N2) R44.1
$2I1098\$3N953: C82.2(N2) R45.1
$2I1098\$3N954: C83.2(N2) R46.1
$2I1098\$3N955: C84.2(N2) R47.1
$2I1098\$3N956: C85.2(N2) R48.1
$2I1098\$3N957: C86.2(N2) R49.1
$2I1098\$4N859: C117.2(N2) R74.1
$2I1098\$4N868: C116.2(N2) R76.1
$2I1098\$4N869: C115.2(N2) R75.1
$2I1098\$4N870: C114.2(N2) R80.1
$2I1098\$4N871: C113.2(N2) R79.1
$2I1098\$4N872: C112.2(N2) R78.1
$2I1098\$4N873: C111.2(N2) R77.1
$2I1098\$4N890: C694.2(N2) R145.1
$2I1098\$4N891: C693.2(N2) R144.1
$2I1098\$4N892: C692.2(N2) R143.1
$2I1116\$2N862: C672.2(N2) R152.1
$2I1116\$2N863: C673.2(N2) R153.1
$2I1116\$2N865: C674.2(N2) R154.1
$2I1116\$2N866: C675.2(N2) R155.1
$2I1116\$2N868: C668.2(N2) R148.1
$2I1116\$2N871: C669.2(N2) R149.1
$2I1116\$2N874: C670.2(N2) R150.1
$2I1116\$2N876: C671.2(N2) R151.1
$2I1116\$2N888: C685.2(N2) R138.1
$2I1116\$2N891: C684.2(N2) R137.1
$3I643\$4N792: C695.2(N2) C699.2(N2) R156.1 U1.R28
$3I643\_DELD: U1.B22
$3I643\_FULL: U1.B23
$3I643\_LRND: U1.A22
$3I643\_NFAD: U1.C22
$3I643\_THDO0: U1.A5
$3I643\_THDO1: U1.B6
$3I643\_THDO2: U1.A6
$3I643\_THDO3: U1.C7
$3I643\CAM_VSSA: C695.1 C699.1 U1.R31
$3I643\MPL_1: RA24.8(N8) U1.AJ15
$3I643\MPL_2: RA24.7 U1.AJ24
$3I643\MPL_3: RA24.6 U1.AK15
$3I643\MPL_4: RA24.5 U1.AK25
$3I643\MPL_5: RA22.8(N8) U1.AL14
$3I643\MPL_6: RA22.7 U1.AL26
$3I643\THDI0: RA21.5 U1.C4
$3I643\THDI1: RA21.6 U1.C5
$3I643\THDI2: RA21.7 U1.B5
$3I643\THDI3: RA21.8(N8) U1.C6
$4I822\$4N792: C696.2(N2) C700.2(N2) R157.1 U2.R28
$4I822\_DELD: U2.B22
$4I822\_FULL: U2.B23
$4I822\_LRND: U2.A22
$4I822\_NFAD: U2.C22
$4I822\_THDO0: U2.A5
$4I822\_THDO1: U2.B6
$4I822\_THDO2: U2.A6
$4I822\_THDO3: U2.C7
$4I822\CAM_VSSA: C696.1 C700.1 U2.R31
$4I822\MPL_1: RA28.8(N8) U2.AJ15
$4I822\MPL_2: RA28.7 U2.AJ24
$4I822\MPL_3: RA28.6 U2.AK15
$4I822\MPL_4: RA28.5 U2.AK25
$4I822\MPL_5: RA26.8(N8) U2.AL14
$4I822\MPL_6: RA26.7 U2.AL26
$4I822\THDI0: RA25.5 U2.C4
$4I822\THDI1: RA25.6 U2.C5
$4I822\THDI2: RA25.7 U2.B5
$4I822\THDI3: RA25.8(N8) U2.C6
$5I996\$4N792: C697.2(N2) C701.2(N2) R158.1 U3.R28
$5I996\_DELD: U3.B22
$5I996\_FULL: U3.B23
$5I996\_LRND: U3.A22
$5I996\_NFAD: U3.C22
$5I996\_THDO0: U3.A5
$5I996\_THDO1: U3.B6
$5I996\_THDO2: U3.A6
$5I996\_THDO3: U3.C7
$5I996\CAM_VSSA: C697.1 C701.1 U3.R31
$5I996\MPL_1: RA31.8(N8) U3.AJ15
$5I996\MPL_2: RA31.7 U3.AJ24
$5I996\MPL_3: RA31.6 U3.AK15
$5I996\MPL_4: RA31.5 U3.AK25
$5I996\MPL_5: RA30.8(N8) U3.AL14
$5I996\MPL_6: RA30.7 U3.AL26
$5I996\THDI0: RA29.5 U3.C4
$5I996\THDI1: RA29.6 U3.C5
$5I996\THDI2: RA29.7 U3.B5
$5I996\THDI3: RA29.8(N8) U3.C6
$6I7\$4N792: C698.2(N2) C702.2(N2) R159.1 U4.R28
$6I7\_DELD: U4.B22
$6I7\_FULL: U4.B23
$6I7\_LRND: U4.A22
$6I7\_NFAD: U4.C22
$6I7\_THDO0: U4.A5
$6I7\_THDO1: U4.B6
$6I7\_THDO2: U4.A6
$6I7\_THDO3: U4.C7
$6I7\CAM_VSSA: C698.1 C702.1 U4.R31
$6I7\MPL_1: RA34.8(N8) U4.AJ15
$6I7\MPL_2: RA34.7 U4.AJ24
$6I7\MPL_3: RA34.6 U4.AK15
$6I7\MPL_4: RA34.5 U4.AK25
$6I7\MPL_5: RA33.8(N8) U4.AL14
$6I7\MPL_6: RA33.7 U4.AL26
$6I7\THDI0: RA32.5 U4.C4
$6I7\THDI1: RA32.6 U4.C5
$6I7\THDI2: RA32.7 U4.B5
$6I7\THDI3: RA32.8(N8) U4.C6
_HIT_N_0: U1.C11
_HIT_N_1: U2.C11
_HIT_N_2: U3.C11
_MULT_N_0: U1.A8
_MULT_N_1: U2.A8
_MULT_N_2: U3.A8
CAM0_TDO: R187.2(N2) R188.1 U1.AL15 U2.AL17
CAM1_TDO: R188.2(N2) R189.1 U2.AL15 U3.AL17
CAM2_TDO: R189.2(N2) R190.1 U3.AL15 U4.AL17
CAM3_TDO: J1.W1 R190.2(N2) U4.AL15
CAM_BS0: J1.A37 J3.15 R143.2(N2) U1.AL20 U2.AL20 U3.AL20 U4.AL20
CAM_BS1: J1.C37 J3.14 R144.2(N2) U1.AK20 U2.AK20 U3.AK20 U4.AK20
CAM_BS2: J1.E37 J3.13 R145.2(N2) U1.AJ20 U2.AJ20 U3.AJ20 U4.AJ20
CAM_CK_0: J1.R13 R148.2(N2) U1.P31
CAM_CK_1: J1.W13 R149.2(N2) U2.P31
CAM_CK_2: J1.R15 R150.2(N2) U3.P31
CAM_CK_3: J1.W15 R151.2(N2) U4.P31
CAM_CK_4: J1.R17 J5.3 R138.2(N2)
CAM_CK_5: J1.W17(9)
CAM_CK_6: J1.R19
CAM_CK_7: J1.W19
CAM_CKP_0: J1.R23 R155.2(N2) U1.R3
CAM_CKP_1: J1.W23 R154.2(N2) U2.R3
CAM_CKP_2: J1.R25 R153.2(N2) U3.R3
CAM_CKP_3: J1.W25 R152.2(N2) U4.R3
CAM_CKP_4: J1.R27 J6.3 R137.2(N2)
CAM_CKP_5: J1.W27
CAM_CKP_6: J1.R29
CAM_CKP_7: J1.W29
CAM_DQ0: J1.L27 J6.20 R117.2(N2) U1.J2(DQ0) U2.J2(DQ0) U3.J2(DQ0) U4.J2(DQ0)
CAM_DQ1: J1.J27 J6.19 R116.2(N2) U1.J1 U2.J1 U3.J1 U4.J1
CAM_DQ2: J1.L25 J6.21 R115.2(N2) U1.K3 U2.K3 U3.K3 U4.K3
CAM_DQ3: J1.J25 J6.18 R114.2(N2) U1.K2 U2.K2 U3.K2 U4.K2
CAM_DQ4: J1.L23 J6.22 R110.2(N2) U1.K1 U2.K1 U3.K1 U4.K1
CAM_DQ5: J1.J23 J6.17 R113.2(N2) U1.L3 U2.L3 U3.L3 U4.L3
CAM_DQ6: J1.L21 J6.23 R112.2(N2) U1.L2 U2.L2 U3.L2 U4.L2
CAM_DQ7: J1.J21 J6.16 R111.2(N2) U1.L1 U2.L1 U3.L1 U4.L1
CAM_DQ8: J1.L19 J6.24 R125.2(N2) U1.M3 U2.M3 U3.M3 U4.M3
CAM_DQ9: J1.J19 J6.15 R124.2(N2) U1.M2 U2.M2 U3.M2 U4.M2
CAM_DQ10: J1.L17 J6.25 R123.2(N2) U1.M1 U2.M1 U3.M1 U4.M1
CAM_DQ11: J1.J17 J6.14 R122.2(N2) U1.N3 U2.N3 U3.N3 U4.N3
CAM_DQ12: J1.L15 J6.26 R118.2(N2) U1.N2 U2.N2 U3.N2 U4.N2
CAM_DQ13: J1.J15 J6.13 R121.2(N2) U1.N1 U2.N1 U3.N1 U4.N1
CAM_DQ14: J1.L13 J6.27 R120.2(N2) U1.P3 U2.P3 U3.P3 U4.P3
CAM_DQ15: J1.J13 J6.12 R119.2(N2) U1.P2 U2.P2 U3.P2 U4.P2
CAM_DQ16: J1.U11 J6.28 R91.2(N2) U1.V2 U2.V2 U3.V2 U4.V2
CAM_DQ17: J1.W11 J6.11 R90.2(N2) U1.V3 U2.V3 U3.V3 U4.V3
CAM_DQ18: J1.J9 J6.29 R89.2(N2) U1.W1 U2.W1 U3.W1 U4.W1
CAM_DQ19: J1.L9 J6.10 R88.2(N2) U1.W2 U2.W2 U3.W2 U4.W2
CAM_DQ20: J1.N9 J6.30 R99.2(N2) U1.W3 U2.W3 U3.W3 U4.W3
CAM_DQ21: J1.R9 J6.9 R98.2(N2) U1.Y1 U2.Y1 U3.Y1 U4.Y1
CAM_DQ22: J1.U9 J6.31 R97.2(N2) U1.Y2 U2.Y2 U3.Y2 U4.Y2
CAM_DQ23: J1.W9 J6.8 R96.2(N2) U1.Y3 U2.Y3 U3.Y3 U4.Y3
CAM_DQ24: J1.J7 J6.32 R92.2(N2) U1.AA1 U2.AA1 U3.AA1 U4.AA1
CAM_DQ25: J1.L7 J6.7 R95.2(N2) U1.AA2 U2.AA2 U3.AA2 U4.AA2
CAM_DQ26: J1.N7 J6.33 R94.2(N2) U1.AA3 U2.AA3 U3.AA3 U4.AA3
CAM_DQ27: J1.R7 J6.6 R93.2(N2) U1.AB1 U2.AB1 U3.AB1 U4.AB1
CAM_DQ28: J1.U7 J6.34 R106.2(N2) U1.AB2 U2.AB2 U3.AB2 U4.AB2
CAM_DQ29: J1.W7 J6.5 R107.2(N2) U1.AB3 U2.AB3 U3.AB3 U4.AB3
CAM_DQ30: J1.J5 J6.35 R105.2(N2) U1.AC1 U2.AC1 U3.AC1 U4.AC1
CAM_DQ31: J1.L5 J6.4 R104.2(N2) U1.AC2 U2.AC2 U3.AC2 U4.AC2
CAM_DQ32: J1.N5 J3.20 R100.2(N2) RA19.5 U1.AC3 U2.AC3 U3.AC3 U4.AC3
CAM_DQ33: J1.R5 J3.19 R103.2(N2) RA19.6 U1.AD1 U2.AD1 U3.AD1 U4.AD1
CAM_DQ34: J1.U5 J3.21 R102.2(N2) RA19.7 U1.AD2 U2.AD2 U3.AD2 U4.AD2
CAM_DQ35: J1.W5 J3.18 R101.2(N2) RA19.8(N8) U1.AD3 U2.AD3 U3.AD3 U4.AD3
CAM_HIT_N: J1.L29 J5.4 U4.A10
CAM_ID0: J1.N21 R132.1
CAM_ID1: J1.N23 R131.1
CAM_ID2: J1.N25 R128.1
CAM_ID3: J1.N27 R129.1
CAM_ID4: J1.N29 R130.1
CAM_MSK0: J1.R31 J3.30 R77.2(N2) U1.C24 U2.C24 U3.C24 U4.C24
CAM_MSK1: J1.N31 J3.9 R78.2(N2) U1.B25 U2.B25 U3.B25 U4.B25
CAM_MSK2: J1.L31 J3.31 R79.2(N2) U1.C25 U2.C25 U3.C25 U4.C25
CAM_MSK3: J1.J31 J3.8 R80.2(N2) U1.B26 U2.B26 U3.B26 U4.B26
CAM_MULT_N: J1.J29 J5.35 U4.C9
CAM_OE_N: J1.J11 J3.17 R126.2(N2) U1.R1 U2.R1 U3.R1 U4.R1
CAM_RDY: J1.R11 J5.5 R109.2(N2) R136.2(N2) U1.T3 U2.T3 U3.T3 U4.T3
CAM_SA0: J1.W39 J5.20 U1.A12 U2.A12 U3.A12 U4.A12
CAM_SA1: J1.U39 J5.19 U1.C13 U2.C13 U3.C13 U4.C13
CAM_SA2: J1.R39 J5.21 U1.B13 U2.B13 U3.B13 U4.B13
CAM_SA3: J1.N39 J5.18 U1.A13 U2.A13 U3.A13 U4.A13
CAM_SA4: J1.L39 J5.22 U1.C14 U2.C14 U3.C14 U4.C14
CAM_SA5: J1.J39 J5.17 U1.B14 U2.B14 U3.B14 U4.B14
CAM_SA6: J1.W37 J5.23 U1.A14 U2.A14 U3.A14 U4.A14
CAM_SA7: J1.U37 J5.16 U1.C15 U2.C15 U3.C15 U4.C15
CAM_SA8: J1.R37 J5.24 U1.B15 U2.B15 U3.B15 U4.B15
CAM_SA9: J1.N37 J5.15 U1.A15 U2.A15 U3.A15 U4.A15
CAM_SA10: J1.L37 J5.25 U1.C16 U2.C16 U3.C16 U4.C16
CAM_SA11: J1.J37 J5.14 U1.B16 U2.B16 U3.B16 U4.B16
CAM_SA12: J1.W35 J5.26 U1.A16 U2.A16 U3.A16 U4.A16
CAM_SA13: J1.U35 J5.13 U1.C17 U2.C17 U3.C17 U4.C17
CAM_SA14: J1.R35 J5.27 U1.B17 U2.B17 U3.B17 U4.B17
CAM_SA15: J1.N35 J5.12 U1.A17 U2.A17 U3.A17 U4.A17
CAM_SA16: J1.L35 J5.28 R140.1 U1.A18 U2.A18 U3.A18 U4.A18
CAM_SA17: J1.J35 J5.11 R141.1 U1.C18 U2.C18 U3.C18 U4.C18
CAM_SA18: J1.W33 J5.29 RA20.5 U1.B18 U2.B18 U3.B18 U4.B18
CAM_SA19: J1.U33 J5.10 RA20.6 U1.A19 U2.A19 U3.A19 U4.A19
CAM_SA20: J1.R33 J5.30 RA20.7 U1.B19 U2.B19 U3.B19 U4.B19
CAM_SA21: J1.N33 J5.9 RA20.8(N8) U1.C19 U2.C19 U3.C19 U4.C19
CAM_SA22: J1.L33 J5.31 U1.A20 U2.A20 U3.A20 U4.A20
CAM_SA23: J1.J33 J5.8 U1.B20 U2.B20 U3.B20 U4.B20
CAM_SA24: J1.W31 J5.32 U1.C20 U2.C20 U3.C20 U4.C20
CAM_SA25: J1.U31 J5.7 U1.A21 U2.A21 U3.A21 U4.A21
CAM_SD0: J1.G35 J3.32 R62.2(N2) U1.C26 U2.C26 U3.C26 U4.C26
CAM_SD1: J1.E35 J3.7 R63.2(N2) U1.B27 U2.B27 U3.B27 U4.B27
CAM_SD2: J1.C35 J3.33 R64.2(N2) U1.C27 U2.C27 U3.C27 U4.C27
CAM_SD3: J1.A35 J3.6 R65.2(N2) U1.C28 U2.C28 U3.C28 U4.C28
CAM_SD4: J1.G33 J3.34 R66.2(N2) U1.D29 U2.D29 U3.D29 U4.D29
CAM_SD5: J1.E33 J3.5 R67.2(N2) U1.E29 U2.E29 U3.E29 U4.E29
CAM_SD6: J1.C33 J3.35 R68.2(N2) U1.E30 U2.E30 U3.E30 U4.E30
CAM_SD7: J1.A33 J3.4 R69.2(N2) U1.F29 U2.F29 U3.F29 U4.F29
CAM_SD8: J1.G31 J4.20 R70.2(N2) U1.F30 U2.F30 U3.F30 U4.F30
CAM_SD9: J1.E31 J4.19 R71.2(N2) U1.F31 U2.F31 U3.F31 U4.F31
CAM_SD10: J1.C31 J4.21 R72.2(N2) U1.G29 U2.G29 U3.G29 U4.G29
CAM_SD11: J1.A31 J4.18 R73.2(N2) U1.G30 U2.G30 U3.G30 U4.G30
CAM_SD12: J1.G29 J4.22 R50.2(N2) U1.G31 U2.G31 U3.G31 U4.G31
CAM_SD13: J1.E29 J4.17 R51.2(N2) U1.H29 U2.H29 U3.H29 U4.H29
CAM_SD14: J1.C29 J4.23 R52.2(N2) U1.H30 U2.H30 U3.H30 U4.H30
CAM_SD15: J1.A29 J4.16 R53.2(N2) U1.H31 U2.H31 U3.H31 U4.H31
CAM_SD16: J1.G27 J4.24 R54.2(N2) U1.J29 U2.J29 U3.J29 U4.J29
CAM_SD17: J1.E27 J4.15 R55.2(N2) U1.J30 U2.J30 U3.J30 U4.J30
CAM_SD18: J1.C27 J4.25 R56.2(N2) U1.J31 U2.J31 U3.J31 U4.J31
CAM_SD19: J1.A27 J4.14 R57.2(N2) U1.K29 U2.K29 U3.K29 U4.K29
CAM_SD20: J1.G25 J4.26 R58.2(N2) U1.K30 U2.K30 U3.K30 U4.K30
CAM_SD21: J1.E25 J4.13 R59.2(N2) U1.K31 U2.K31 U3.K31 U4.K31
CAM_SD22: J1.C25 J4.27 R60.2(N2) U1.L29 U2.L29 U3.L29 U4.L29
CAM_SD23: J1.A25 J4.12 R61.2(N2) U1.L30 U2.L30 U3.L30 U4.L30
CAM_SD24: J1.G23 J4.28 R38.2(N2) U1.L31 U2.L31 U3.L31 U4.L31
CAM_SD25: J1.E23 J4.11 R39.2(N2) U1.M29 U2.M29 U3.M29 U4.M29
CAM_SD26: J1.C23 J4.29 R40.2(N2) U1.M30 U2.M30 U3.M30 U4.M30
CAM_SD27: J1.A23 J4.10 R41.2(N2) U1.M31 U2.M31 U3.M31 U4.M31
CAM_SD28: J1.G21 J4.30 R42.2(N2) U1.N29 U2.N29 U3.N29 U4.N29
CAM_SD29: J1.E21 J4.9 R43.2(N2) U1.N30 U2.N30 U3.N30 U4.N30
CAM_SD30: J1.C21 J4.31 R44.2(N2) U1.N31 U2.N31 U3.N31 U4.N31
CAM_SD31: J1.A21 J4.8 R45.2(N2) U1.P29 U2.P29 U3.P29 U4.P29
CAM_SD32: J1.G19 J4.32 R46.2(N2) U1.T29 U2.T29 U3.T29 U4.T29
CAM_SD33: J1.E19 J4.7 R47.2(N2) U1.T30 U2.T30 U3.T30 U4.T30
CAM_SD34: J1.C19 J4.33 R48.2(N2) U1.U31 U2.U31 U3.U31 U4.U31
CAM_SD35: J1.A19 J4.6 R49.2(N2) U1.U30 U2.U30 U3.U30 U4.U30
CAM_SD36: J1.G17 J4.34 R26.2(N2) U1.U29 U2.U29 U3.U29 U4.U29
CAM_SD37: J1.E17 J4.5 R27.2(N2) U1.V31 U2.V31 U3.V31 U4.V31
CAM_SD38: J1.C17 J4.35 R28.2(N2) U1.V30 U2.V30 U3.V30 U4.V30
CAM_SD39: J1.A17 J4.4 R29.2(N2) U1.V29 U2.V29 U3.V29 U4.V29
CAM_SD40: J1.G15 J2.20 R30.2(N2) U1.W30 U2.W30 U3.W30 U4.W30
CAM_SD41: J1.E15 J2.19 R31.2(N2) U1.W29 U2.W29 U3.W29 U4.W29
CAM_SD42: J1.C15 J2.21 R32.2(N2) U1.Y31 U2.Y31 U3.Y31 U4.Y31
CAM_SD43: J1.A15 J2.18 R33.2(N2) U1.Y30 U2.Y30 U3.Y30 U4.Y30
CAM_SD44: J1.G13 J2.22 R34.2(N2) U1.Y29 U2.Y29 U3.Y29 U4.Y29
CAM_SD45: J1.E13 J2.17 R35.2(N2) U1.AA31 U2.AA31 U3.AA31 U4.AA31
CAM_SD46: J1.C13 J2.23 R36.2(N2) U1.AA30 U2.AA30 U3.AA30 U4.AA30
CAM_SD47: J1.A13 J2.16 R37.2(N2) U1.AA29 U2.AA29 U3.AA29 U4.AA29
CAM_SD48: J1.G11 J2.24 R14.2(N2) U1.AB31 U2.AB31 U3.AB31 U4.AB31
CAM_SD49: J1.E11 J2.15 R15.2(N2) U1.AB30 U2.AB30 U3.AB30 U4.AB30
CAM_SD50: J1.C11 J2.25 R16.2(N2) U1.AB29 U2.AB29 U3.AB29 U4.AB29
CAM_SD51: J1.A11 J2.14 R17.2(N2) U1.AC31 U2.AC31 U3.AC31 U4.AC31
CAM_SD52: J1.G9 J2.26 R18.2(N2) U1.AC30 U2.AC30 U3.AC30 U4.AC30
CAM_SD53: J1.E9 J2.13 R19.2(N2) U1.AC29 U2.AC29 U3.AC29 U4.AC29
CAM_SD54: J1.C9 J2.27 R20.2(N2) U1.AD31 U2.AD31 U3.AD31 U4.AD31
CAM_SD55: J1.A9 J2.12 R21.2(N2) U1.AD30 U2.AD30 U3.AD30 U4.AD30
CAM_SD56: J1.G7 J2.28 R22.2(N2) U1.AD29 U2.AD29 U3.AD29 U4.AD29
CAM_SD57: J1.E7 J2.11 R23.2(N2) U1.AE31 U2.AE31 U3.AE31 U4.AE31
CAM_SD58: J1.C7 J2.29 R24.2(N2) U1.AE30 U2.AE30 U3.AE30 U4.AE30
CAM_SD59: J1.A7 J2.10 R25.2(N2) U1.AF31 U2.AF31 U3.AF31 U4.AF31
CAM_SD60: J1.G5 J2.30 R2.2(N2) U1.AE29 U2.AE29 U3.AE29 U4.AE29
CAM_SD61: J1.E5 J2.9 R3.2(N2) U1.AF30 U2.AF30 U3.AF30 U4.AF30
CAM_SD62: J1.C5 J2.31 R4.2(N2) U1.AG31 U2.AG31 U3.AG31 U4.AG31
CAM_SD63: J1.A5 J2.8 R5.2(N2) U1.AF29 U2.AF29 U3.AF29 U4.AF29
CAM_SD64: J1.G3 J2.32 R6.2(N2) U1.AG30 U2.AG30 U3.AG30 U4.AG30
CAM_SD65: J1.E3 J2.7 R7.2(N2) U1.AG29 U2.AG29 U3.AG29 U4.AG29
CAM_SD66: J1.C3 J2.33 R8.2(N2) U1.AH30 U2.AH30 U3.AH30 U4.AH30
CAM_SD67: J1.A3 J2.6 R9.2(N2) U1.AH29 U2.AH29 U3.AH29 U4.AH29
CAM_SD68: J1.G1 J2.34 R10.2(N2) U1.AJ28 U2.AJ28 U3.AJ28 U4.AJ28
CAM_SD69: J1.E1 J2.5 R11.2(N2) U1.AK28 U2.AK28 U3.AK28 U4.AK28
CAM_SD70: J2.35 R12.2(N2) R134.2(N2) R147.2(N2) U1.AJ27 U2.AJ27 U3.AJ27 U4.AJ27
CAM_SD71: J2.4 R13.2(N2) R133.2(N2) R146.2(N2) U1.AK27 U2.AK27 U3.AK27 U4.AK27
CAM_SS_N: J1.R21 J3.11 R74.2(N2) U1.R29 U2.R29 U3.R29 U4.R29
CAM_TA_N: J1.N11 J5.34 R81.2(N2) R108.2(N2) U1.T2 U2.T2 U3.T2 U4.T2
CAM_TAG0: J1.J1 J3.29 R76.2(N2) U1.AK26 U2.AK26 U3.AK26 U4.AK26
CAM_TAG1: J1.L1 J3.10 R75.2(N2) U1.AJ25 U2.AJ25 U3.AJ25 U4.AJ25
CAM_TS_N: J1.L11 J3.16 R127.2(N2) U1.R2 U2.R2 U3.R2 U4.R2
CAMBRD_I2C_A0: J1.A39 R184.2(N2) U6.1
CAMBRD_I2C_A1: J1.C39 R183.2(N2) U6.2
CAMBRD_I2C_A2: J1.E39 R176.2(N2) U6.3
CAMBRD_SCL: J1.G39 R185.2(N2) U6.6
CAMBRD_SDA: J1.G37 R186.2(N2) U6.5
HIN0_0: RA3.7 U1.A11
HIN0_1: RA11.8(N8) U2.A11
HIN0_2: RA12.5 U3.A11
HIN1_0: RA3.8(N8) U1.C12
HIN1_1: RA7.5 U2.C12
HIN2_0: RA6.5 U1.B12
HIT_N_3: J3.23 R165.2(N2)
HIT_N_3_SRC: R165.1 U4.C11
HON_0: R83.2(N2) R178.1 U1.A10 U2.B12 U3.B12 U4.B12
HON_1: R84.2(N2) R179.1 U2.A10 U3.C12 U4.C12
HON_2: R139.2(N2) R181.1 U3.A10 U4.A11
HSN_0: RA3.6 U1.B11
HSN_1: RA11.7 U2.B11
HSN_2: RA15.8(N8) U3.B11
HSN_3: RA27.5 U4.B11
I2C_WP: J7.1 R175.2(N2) U6.7(WP)
ID0_0: RA2.6 U1.B7
ID0_1: R1.2(N2) R166.2(N2) U2.B7
ID0_2: R169.2(N2) R170.2(N2) U3.B7
ID0_3: R171.2(N2) R172.2(N2) U4.B7
ID1_0: RA2.7 U1.C8
ID1_1: RA9.8(N8) U2.C8
ID1_2: R167.2(N2) R168.2(N2) U3.C8
ID1_3: R173.2(N2) R174.2(N2) U4.C8
ID2_0: RA2.8(N8) U1.A7
ID2_1: RA10.5 U2.A7
ID2_2: RA18.6 U3.A7
ID2_3: RA23.6 U4.A7
ID3_0: RA4.5 U1.B8
ID3_1: RA10.6 U2.B8
ID3_2: RA18.7 U3.B8
ID3_3: RA23.7 U4.B8
MIN0_0: RA4.7 U1.C10
MIN0_1: RA10.8(N8) U2.C10
MIN0_2: RA15.5 U3.C10
MIN1_0: RA4.8(N8) U1.A9
MIN1_1: RA11.5 U2.A9
MIN1_2: RA15.6 U3.A9
MIN2_0: RA3.5 U1.B10
MIN2_1: RA11.6 U2.B10
MIN2_2: RA15.7 U3.B10
MODE0_0: RA1.7 U1.AE3
MODE0_1: RA9.5 U2.AE3
MODE0_2: RA14.7 U3.AE3
MODE0_3: RA14.5 U4.AE3
MODE1_0: RA1.8(N8) U1.AE2
MODE1_1: RA9.6 U2.AE2
MODE1_2: RA14.8(N8) U3.AE2
MODE1_3: RA14.6 U4.AE2
MODE2_0: RA2.5 U1.AE1
MODE2_1: RA9.7 U2.AE1
MODE2_2: RA18.5 U3.AE1
MODE2_3: RA23.5 U4.AE1
MON_0: R82.2(N2) R177.1 U1.C9 U4.B10
MON_1: R85.2(N2) R180.1 U2.C9 U4.A9
MON_2: R142.2(N2) R182.1 U3.C9 U4.C10
MSN_0: RA4.6 U1.B9
MSN_1: RA10.7 U2.B9
MSN_2: RA18.8(N8) U3.B9
MSN_3: RA23.8(N8) U4.B9
MULT_N_3: J3.22 R164.2(N2)
MULT_N_3_SRC: R164.1 U4.A8
NPB_SD70: J1.C1 R134.1
NPB_SD71: J1.A1 R133.1
NTBL_0: J3.27 R160.2(N2)
NTBL_0_SRC: R160.1 U1.A23
NTBL_1: J3.26 R161.2(N2)
NTBL_1_SRC: R161.1 U2.A23
NTBL_2: J3.25 R162.2(N2)
NTBL_2_SRC: R162.1 U3.A23
NTBL_3: J3.24 R163.2(N2)
NTBL_3_SRC: R163.1 U4.A23
OESN_0: RA5.6 U1.R30
OESN_1: RA8.6 U2.R30
OESN_2: RA13.6 U3.R30
OESN_3: RA16.6 U4.R30
OP0_0: RA6.6 U1.AL25
OP0_1: RA7.6 U2.AL25
OP0_2: RA12.6 U3.AL25
OP0_3: RA27.6 U4.AL25
OP1_0: RA6.7 U1.AK24
OP1_1: RA7.7 U2.AK24
OP1_2: RA12.7 U3.AK24
OP1_3: RA27.7 U4.AK24
OP2_0: RA6.8(N8) U1.AJ23
OP2_1: RA7.8(N8) U2.AJ23
OP2_2: RA12.8(N8) U3.AJ23
OP2_3: RA27.8(N8) U4.AJ23
OP3_0: RA5.5 U1.AL24
OP3_1: RA8.5 U2.AL24
OP3_2: RA13.5 U3.AL24
OP3_3: RA16.5 U4.AL24
PT_ADJUST: PS1.14 R86.2(N2) R87.2(N2)
PT_SENSE: PS1.1 R86.1 R135.1
PT_STBY_N: PS1.3(~STBY) Q1.3
RDYS_0: RA5.8(N8) U1.AL21
RDYS_1: RA8.8(N8) U2.AL21
RDYS_2: RA13.8(N8) U3.AL21
RDYS_3: RA16.8(N8) U4.AL21
RST_N: J1.U3 J3.12 U1.AF1 U2.AF1 U3.AF1 U4.AF1
TASN_0: RA5.7 U1.AK21
TASN_1: RA8.7 U2.AK21
TASN_2: RA13.7 U3.AK21
TASN_3: RA16.7 U4.AK21
TCK: J1.N1 U1.AK16 U2.AK16 U3.AK16 U4.AK16
TDI_CAM: J1.R1 R187.1 U1.AL17
TMS: J1.U1 U1.AL16 U2.AL16 U3.AL16 U4.AL16
